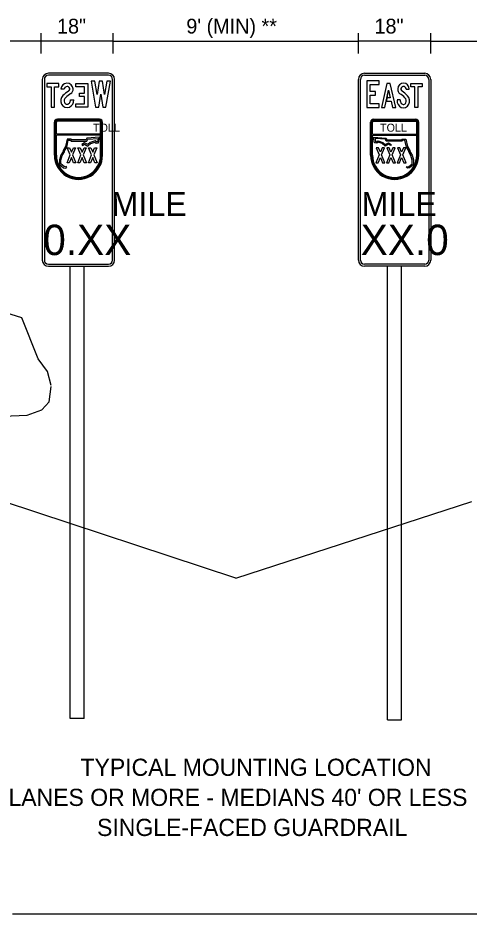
# Model space of a CAD drawing. Extents: x 57428 to 58066, y 11696 to 12105.
# Drawn here: x 57710.6 to 57796, y 11934.3 to 12103.9 of the extents above; entities that cross this region are included whole.
import ezdxf

# ---------------------------------------------------------------- set-up
doc = ezdxf.new("R2010")
doc.units = 0
for name, color, linetype in [('62', 7, 'Continuous'), ('DimLines_dp', 7, 'Continuous'), ('NonPlottingEle_dp', 7, 'Continuous'), ('SignPanel', 7, 'Continuous'), ('TextMisc', 7, 'Continuous'), ('TextTables', 7, 'Continuous'), ('XSGrdLine_ex', 7, 'Continuous')]:
    doc.layers.add(name, color=color, linetype=linetype)

msp = doc.modelspace()

# ---------------------------------------------------------------- linework, layer by layer
at = {"layer": '62'}
msp.add_lwpolyline([(57716.92, 12034.31), (57716.22, 12036.91), (57714.42, 12039.32), (57711.32, 12047.07), (57706.22, 12048.67), (57702.51, 12048.17), (57697.71, 12040.32), (57696.21, 12037.11), (57696.01, 12033.61), (57697.21, 12030.61), (57700.31, 12028.9), (57706.22, 12028.4), (57712.32, 12028.7), (57715.12, 12029.7), (57716.52, 12031.21), (57716.92, 12034.11)], dxfattribs=at)
at = {"layer": 'DimLines_dp'}
for p, q in [((57714.97, 12097.15), (57714.97, 12100.98)), ((57728.65, 12097.15), (57728.65, 12100.98)), ((57775.06, 12097.15), (57775.06, 12100.98)), ((57788.75, 12097.15), (57788.75, 12100.98)), ((57714.97, 12099.43), (57645.43, 12099.43)), ((57728.65, 12099.43), (57714.97, 12099.43)), ((57728.65, 12099.43), (57775.06, 12099.43)), ((57788.75, 12099.43), (57775.06, 12099.43)), ((57788.75, 12099.43), (57858.29, 12099.43))]:
    msp.add_line(p, q, dxfattribs=at)
at = {"layer": 'NonPlottingEle_dp'}
for p, q in [((57720.48, 12008.18), (57720.48, 12056.87)), ((57723.14, 12007.3), (57723.14, 12056.87)), ((57780.58, 12007.16), (57780.58, 12056.87)), ((57783.24, 12008.02), (57783.24, 12056.87)), ((57720.48, 11971.28), (57720.48, 12008.18)), ((57783.24, 11971.03), (57783.24, 12008.02)), ((57723.14, 11971.28), (57723.14, 12007.3)), ((57780.58, 11971.03), (57780.58, 12007.16)), ((57723.14, 11971.28), (57720.48, 11971.28)), ((57780.58, 11971.03), (57783.24, 11971.03))]:
    msp.add_line(p, q, dxfattribs=at)
at = {"layer": 'SignPanel'}
for p, q in [((57719.37, 12090.36), (57718.75, 12090.36)), ((57719.37, 12090.36), (57718.75, 12090.36)), ((57719.37, 12090.36), (57718.75, 12090.36)), ((57784.1, 12090.36), (57784.68, 12090.36)), ((57784.1, 12090.36), (57784.68, 12090.36)), ((57784.1, 12090.36), (57784.68, 12090.36)), ((57720.56, 12088.35), (57721.19, 12088.35)), ((57720.56, 12088.35), (57721.19, 12088.35)), ((57720.56, 12088.35), (57721.19, 12088.35)), ((57782.96, 12088.32), (57782.37, 12088.32)), ((57782.96, 12088.32), (57782.37, 12088.32)), ((57782.96, 12088.32), (57782.37, 12088.32)), ((57717.5, 12077.85), (57717.5, 12084.13)), ((57717.69, 12077.85), (57717.69, 12084.13)), ((57717.88, 12081.85), (57717.88, 12084.13)), ((57726.05, 12084.7), (57718.07, 12084.7)), ((57726.05, 12084.51), (57718.07, 12084.51)), ((57726.05, 12084.32), (57718.07, 12084.32)), ((57726.24, 12081.85), (57726.24, 12084.13)), ((57726.43, 12077.85), (57726.43, 12084.13)), ((57726.62, 12077.85), (57726.62, 12084.13)), ((57777.35, 12077.85), (57777.35, 12084.13)), ((57777.54, 12077.85), (57777.54, 12084.13)), ((57777.72, 12081.85), (57777.72, 12084.13)), ((57777.92, 12084.7), (57785.9, 12084.7)), ((57777.92, 12084.51), (57785.9, 12084.51)), ((57777.92, 12084.32), (57785.9, 12084.32)), ((57786.09, 12081.85), (57786.09, 12084.13)), ((57786.28, 12077.85), (57786.28, 12084.13)), ((57786.47, 12077.85), (57786.47, 12084.13)), ((57726.24, 12081.85), (57717.88, 12081.85)), ((57717.88, 12077.85), (57717.88, 12081.66)), ((57726.24, 12081.66), (57717.88, 12081.66)), ((57719.95, 12080.92), (57719.62, 12079.49)), ((57719.83, 12079.4), (57720.13, 12080.69)), ((57720.68, 12080.92), (57719.95, 12080.92)), ((57720.13, 12080.69), (57720.56, 12080.69)), ((57720.56, 12080.69), (57720.66, 12080.53)), ((57720.66, 12080.53), (57723.67, 12080.53)), ((57720.79, 12080.76), (57720.68, 12080.92)), ((57723.52, 12080.76), (57720.79, 12080.76)), ((57723.65, 12081.11), (57723.52, 12080.76)), ((57726.03, 12081.29), (57723.65, 12081.11)), ((57723.67, 12080.53), (57723.81, 12080.89)), ((57723.81, 12080.89), (57725.76, 12081.04)), ((57725.2, 12080.6), (57724.28, 12080.3)), ((57724.77, 12080.95), (57724.77, 12080.95)), ((57725.47, 12080.38), (57725.2, 12080.6)), ((57725.76, 12081.04), (57725.66, 12080.41)), ((57725.86, 12080.2), (57726.03, 12081.29)), ((57726.24, 12077.85), (57726.24, 12081.66)), ((57777.72, 12081.85), (57786.09, 12081.85)), ((57777.72, 12077.85), (57777.72, 12081.66)), ((57777.72, 12081.66), (57786.09, 12081.66)), ((57778.11, 12080.2), (57777.94, 12081.29)), ((57777.94, 12081.29), (57780.32, 12081.11)), ((57780.16, 12080.89), (57778.21, 12081.04)), ((57778.21, 12081.04), (57778.31, 12080.41)), ((57778.5, 12080.38), (57778.77, 12080.6)), ((57778.77, 12080.6), (57779.69, 12080.3)), ((57779.2, 12080.95), (57779.2, 12080.95)), ((57780.3, 12080.53), (57780.16, 12080.89)), ((57783.31, 12080.53), (57780.3, 12080.53)), ((57780.32, 12081.11), (57780.45, 12080.76)), ((57780.45, 12080.76), (57783.18, 12080.76)), ((57783.18, 12080.76), (57783.29, 12080.92)), ((57783.29, 12080.92), (57784.02, 12080.92)), ((57783.41, 12080.69), (57783.31, 12080.53)), ((57783.84, 12080.69), (57783.41, 12080.69)), ((57784.14, 12079.4), (57783.84, 12080.69)), ((57784.02, 12080.92), (57784.35, 12079.49)), ((57786.09, 12077.85), (57786.09, 12081.66)), ((57719.62, 12079.49), (57719.16, 12078.76)), ((57719.39, 12078.69), (57719.83, 12079.4)), ((57723.22, 12080.24), (57722.72, 12079.9)), ((57722.72, 12079.9), (57722.85, 12079.71)), ((57722.85, 12079.71), (57723.23, 12079.97)), ((57723.83, 12079.88), (57723.22, 12080.24)), ((57723.23, 12079.97), (57723.86, 12079.6)), ((57724.28, 12080.3), (57723.83, 12079.88)), ((57723.86, 12079.6), (57724.4, 12080.1)), ((57724.4, 12080.1), (57725.15, 12080.34)), ((57725.15, 12080.34), (57725.4, 12080.15)), ((57725.4, 12080.15), (57725.86, 12080.2)), ((57725.66, 12080.41), (57725.47, 12080.38)), ((57778.56, 12080.15), (57778.11, 12080.2)), ((57778.31, 12080.41), (57778.5, 12080.38)), ((57778.81, 12080.34), (57778.56, 12080.15)), ((57779.57, 12080.1), (57778.81, 12080.34)), ((57780.11, 12079.6), (57779.57, 12080.1)), ((57779.69, 12080.3), (57780.14, 12079.88)), ((57780.74, 12079.97), (57780.11, 12079.6)), ((57780.14, 12079.88), (57780.75, 12080.24)), ((57781.12, 12079.71), (57780.74, 12079.97)), ((57780.75, 12080.24), (57781.25, 12079.9)), ((57781.25, 12079.9), (57781.12, 12079.71)), ((57784.58, 12078.69), (57784.14, 12079.4)), ((57784.35, 12079.49), (57784.81, 12078.76)), ((57718.75, 12077.9), (57718.5, 12076.98)), ((57718.73, 12076.95), (57718.97, 12077.81)), ((57719.16, 12078.57), (57718.75, 12077.9)), ((57718.97, 12077.81), (57719.39, 12078.51)), ((57719.16, 12078.76), (57719.16, 12078.57)), ((57719.39, 12078.51), (57719.39, 12078.69)), ((57784.58, 12078.51), (57784.58, 12078.69)), ((57785, 12077.81), (57784.58, 12078.51)), ((57784.81, 12078.76), (57784.81, 12078.57)), ((57784.81, 12078.57), (57785.22, 12077.9)), ((57785.24, 12076.95), (57785, 12077.81)), ((57785.22, 12077.9), (57785.47, 12076.98)), ((57718.5, 12076.98), (57718.5, 12076.12)), ((57718.5, 12076.12), (57719.25, 12075.5)), ((57718.73, 12076.22), (57718.73, 12076.95)), ((57719.36, 12075.71), (57718.73, 12076.22)), ((57719.25, 12075.5), (57719.61, 12075.41)), ((57719.56, 12075.66), (57719.36, 12075.71)), ((57719.71, 12075.76), (57719.56, 12075.66)), ((57719.61, 12075.41), (57719.84, 12075.57)), ((57719.84, 12075.57), (57719.71, 12075.76)), ((57784.13, 12075.57), (57784.26, 12075.76)), ((57784.36, 12075.41), (57784.13, 12075.57)), ((57784.26, 12075.76), (57784.41, 12075.66)), ((57784.72, 12075.5), (57784.36, 12075.41)), ((57784.41, 12075.66), (57784.61, 12075.71)), ((57784.61, 12075.71), (57785.24, 12076.22)), ((57785.47, 12076.12), (57784.72, 12075.5)), ((57785.24, 12076.22), (57785.24, 12076.95)), ((57785.47, 12076.98), (57785.47, 12076.12))]:
    msp.add_line(p, q, dxfattribs=at)
for points in [[(57727.76, 12093.37), (57716.36, 12093.37)], [(57727.76, 12092.99), (57716.36, 12092.99)], [(57776.2, 12093.37), (57787.61, 12093.37)], [(57776.2, 12092.99), (57787.61, 12092.99)], [(57715.22, 12092.23), (57715.22, 12058.01)], [(57715.6, 12092.23), (57715.6, 12058.01)], [(57728.52, 12058.01), (57728.52, 12092.23)], [(57728.9, 12058.01), (57728.9, 12092.23)], [(57775.06, 12058.01), (57775.06, 12092.23)], [(57775.44, 12058.01), (57775.44, 12092.23)], [(57788.37, 12092.23), (57788.37, 12058.01)], [(57788.75, 12092.23), (57788.75, 12058.01)], [(57716.36, 12057.25), (57727.76, 12057.25)], [(57716.36, 12056.87), (57727.76, 12056.87)], [(57787.61, 12057.25), (57776.2, 12057.25)], [(57787.61, 12056.87), (57776.2, 12056.87)]]:
    msp.add_lwpolyline(points, dxfattribs=at)
for points in [[(57717.51, 12090.81), (57718.33, 12090.81), (57718.33, 12091.44), (57716.07, 12091.44), (57716.07, 12090.81), (57716.89, 12090.81), (57716.89, 12086.94), (57717.51, 12086.94)], [(57717.51, 12090.81), (57718.33, 12090.81), (57718.33, 12091.44), (57716.07, 12091.44), (57716.07, 12090.81), (57716.89, 12090.81), (57716.89, 12086.94), (57717.51, 12086.94)], [(57717.51, 12090.81), (57718.33, 12090.81), (57718.33, 12091.44), (57716.07, 12091.44), (57716.07, 12090.81), (57716.89, 12090.81), (57716.89, 12086.94), (57717.51, 12086.94)], [(57723.21, 12087.57), (57723.21, 12089.01), (57722.24, 12089.01), (57722.24, 12089.64), (57723.21, 12089.64), (57723.21, 12090.81), (57721.57, 12090.81), (57721.57, 12091.44), (57723.84, 12091.44), (57723.84, 12086.94), (57721.57, 12086.94), (57721.57, 12087.57)], [(57723.21, 12087.57), (57723.21, 12089.01), (57722.24, 12089.01), (57722.24, 12089.64), (57723.21, 12089.64), (57723.21, 12090.81), (57721.57, 12090.81), (57721.57, 12091.44), (57723.84, 12091.44), (57723.84, 12086.94), (57721.57, 12086.94), (57721.57, 12087.57)], [(57723.21, 12087.57), (57723.21, 12089.01), (57722.24, 12089.01), (57722.24, 12089.64), (57723.21, 12089.64), (57723.21, 12090.81), (57721.57, 12090.81), (57721.57, 12091.44), (57723.84, 12091.44), (57723.84, 12086.94), (57721.57, 12086.94), (57721.57, 12087.57)], [(57727, 12089.33), (57726.59, 12091.89), (57725.99, 12091.89), (57725.59, 12089.33), (57725.13, 12091.89), (57724.44, 12091.89), (57725.31, 12086.94), (57725.9, 12086.94), (57726.29, 12089.42), (57726.68, 12086.94), (57727.27, 12086.94), (57728.14, 12091.89), (57727.45, 12091.89)], [(57727, 12089.33), (57726.59, 12091.89), (57725.99, 12091.89), (57725.59, 12089.33), (57725.13, 12091.89), (57724.44, 12091.89), (57725.31, 12086.94), (57725.9, 12086.94), (57726.29, 12089.42), (57726.68, 12086.94), (57727.27, 12086.94), (57728.14, 12091.89), (57727.45, 12091.89)], [(57727, 12089.33), (57726.59, 12091.89), (57725.99, 12091.89), (57725.59, 12089.33), (57725.13, 12091.89), (57724.44, 12091.89), (57725.31, 12086.94), (57725.9, 12086.94), (57726.29, 12089.42), (57726.68, 12086.94), (57727.27, 12086.94), (57728.14, 12091.89), (57727.45, 12091.89)], [(57777.27, 12087.59), (57777.27, 12089.21), (57778.29, 12089.21), (57778.29, 12089.92), (57777.27, 12089.92), (57777.27, 12091.24), (57778.99, 12091.24), (57778.99, 12091.95), (57776.62, 12091.95), (57776.62, 12086.88), (57778.99, 12086.88), (57778.99, 12087.59)], [(57777.27, 12087.59), (57777.27, 12089.21), (57778.29, 12089.21), (57778.29, 12089.92), (57777.27, 12089.92), (57777.27, 12091.24), (57778.99, 12091.24), (57778.99, 12091.95), (57776.62, 12091.95), (57776.62, 12086.88), (57778.99, 12086.88), (57778.99, 12087.59)], [(57777.27, 12087.59), (57777.27, 12089.21), (57778.29, 12089.21), (57778.29, 12089.92), (57777.27, 12089.92), (57777.27, 12091.24), (57778.99, 12091.24), (57778.99, 12091.95), (57776.62, 12091.95), (57776.62, 12086.88), (57778.99, 12086.88), (57778.99, 12087.59)], [(57781.24, 12088.11), (57781.51, 12086.88), (57782.11, 12086.88), (57781.09, 12091.46), (57780.46, 12091.46), (57779.44, 12086.88), (57780.05, 12086.88), (57780.32, 12088.11)], [(57780.47, 12088.75), (57780.32, 12088.11), (57781.24, 12088.11), (57781.51, 12086.88), (57782.11, 12086.88), (57781.09, 12091.46), (57780.46, 12091.46), (57779.44, 12086.88), (57780.05, 12086.88), (57780.78, 12090.16), (57781.09, 12088.75)], [(57780.47, 12088.75), (57780.32, 12088.11), (57781.24, 12088.11), (57781.51, 12086.88), (57782.11, 12086.88), (57781.09, 12091.46), (57780.46, 12091.46), (57779.44, 12086.88), (57780.05, 12086.88), (57780.78, 12090.16), (57781.09, 12088.75)], [(57785.75, 12090.82), (57784.97, 12090.82), (57784.97, 12091.46), (57787.11, 12091.46), (57787.11, 12090.82), (57786.33, 12090.82), (57786.33, 12086.88), (57785.75, 12086.88)], [(57785.75, 12090.82), (57784.97, 12090.82), (57784.97, 12091.46), (57787.11, 12091.46), (57787.11, 12090.82), (57786.33, 12090.82), (57786.33, 12086.88), (57785.75, 12086.88)], [(57785.75, 12090.82), (57784.97, 12090.82), (57784.97, 12091.46), (57787.11, 12091.46), (57787.11, 12090.82), (57786.33, 12090.82), (57786.33, 12086.88), (57785.75, 12086.88)], [(57780.78, 12090.16), (57781.09, 12088.75), (57780.47, 12088.75)], [(57721.14, 12076.44), (57720.73, 12077.41), (57720.32, 12076.44), (57719.9, 12076.44), (57720.52, 12077.92), (57719.95, 12079.29), (57720.37, 12079.29), (57720.73, 12078.43), (57721.09, 12079.29), (57721.52, 12079.29), (57720.95, 12077.92), (57721.57, 12076.44)], [(57723.16, 12076.44), (57722.75, 12077.41), (57722.34, 12076.44), (57721.91, 12076.44), (57722.53, 12077.92), (57721.96, 12079.29), (57722.39, 12079.29), (57722.75, 12078.43), (57723.11, 12079.29), (57723.53, 12079.29), (57722.96, 12077.92), (57723.58, 12076.44)], [(57725.17, 12076.44), (57724.76, 12077.41), (57724.36, 12076.44), (57723.93, 12076.44), (57724.55, 12077.92), (57723.98, 12079.29), (57724.41, 12079.29), (57724.76, 12078.43), (57725.12, 12079.29), (57725.55, 12079.29), (57724.98, 12077.92), (57725.6, 12076.44)], [(57778.8, 12076.44), (57779.21, 12077.41), (57779.61, 12076.44), (57780.04, 12076.44), (57779.42, 12077.92), (57779.99, 12079.29), (57779.56, 12079.29), (57779.21, 12078.43), (57778.85, 12079.29), (57778.42, 12079.29), (57778.99, 12077.92), (57778.37, 12076.44)], [(57780.81, 12076.44), (57781.22, 12077.41), (57781.63, 12076.44), (57782.06, 12076.44), (57781.43, 12077.92), (57782.01, 12079.29), (57781.58, 12079.29), (57781.22, 12078.43), (57780.86, 12079.29), (57780.44, 12079.29), (57781.01, 12077.92), (57780.39, 12076.44)], [(57782.83, 12076.44), (57783.24, 12077.41), (57783.65, 12076.44), (57784.07, 12076.44), (57783.45, 12077.92), (57784.02, 12079.29), (57783.6, 12079.29), (57783.24, 12078.43), (57782.88, 12079.29), (57782.45, 12079.29), (57783.02, 12077.92), (57782.4, 12076.44)]]:
    msp.add_lwpolyline(points, close=True, dxfattribs=at)
for centre, radius, start, end in [((57716.36, 12092.23), 1.14, 90, 180), ((57716.36, 12092.23), 0.76, 90, 180), ((57727.76, 12092.23), 1.14, 0, 90), ((57727.76, 12092.23), 0.76, 0, 90), ((57776.2, 12092.23), 1.14, 90, 180), ((57776.2, 12092.23), 0.76, 90, 180), ((57787.61, 12092.23), 1.14, 0, 90), ((57787.61, 12092.23), 0.76, 0, 90), ((57716.36, 12058.01), 1.14, 180, 270), ((57716.36, 12058.01), 0.76, 180, 270), ((57727.76, 12058.01), 1.14, 270, 0), ((57727.76, 12058.01), 0.76, 270, 0), ((57776.2, 12058.01), 1.14, 180, 270), ((57776.2, 12058.01), 0.76, 180, 270), ((57787.61, 12058.01), 1.14, 270, 360), ((57787.61, 12058.01), 0.76, 270, 360)]:
    msp.add_arc(centre, radius, start, end, dxfattribs=at)
for centre, major_axis, ratio, start_param, end_param in [((57719.9, 12090.33), (0, -1.17), 0.981197, 1.634182, 4.688511), ((57719.9, 12090.33), (0, -1.17), 0.981197, 1.634182, 4.688511), ((57719.9, 12090.33), (0, -1.17), 0.981197, 1.634182, 4.688511), ((57719.91, 12090.32), (0, -0.55), 0.981197, 2.28404, 4.637874), ((57719.91, 12090.32), (0, -0.55), 0.981197, 2.28404, 4.637874), ((57719.91, 12090.32), (0, -0.55), 0.981197, 2.28404, 4.637874), ((57783.59, 12090.33), (0, 1.19), 0.91923, 4.736267, 7.790596), ((57783.59, 12090.33), (0, 1.19), 0.91923, 4.736267, 7.790596), ((57783.59, 12090.33), (0, 1.19), 0.91923, 4.736267, 7.790596), ((57783.59, 12090.32), (0, 0.558), 0.91923, 4.786904, 7.140738), ((57783.59, 12090.32), (0, 0.558), 0.91923, 4.786904, 7.140738), ((57783.59, 12090.32), (0, 0.558), 0.91923, 4.786904, 7.140738), ((57720.1, 12088.17), (0, -1.4), 0.981197, 3.939023, 5.163791), ((57720.1, 12088.17), (0, -1.4), 0.981197, 3.939023, 5.163791), ((57720.1, 12088.17), (0, -1.4), 0.981197, 3.939023, 5.163791), ((57722.22, 12086.2), (0, -4.32), 0.981197, 3.642536, 3.961892), ((57722.22, 12086.2), (0, -4.32), 0.981197, 3.642536, 3.961892), ((57722.22, 12086.2), (0, -4.32), 0.981197, 3.642536, 3.961892), ((57722.75, 12085.51), (0, -4.56), 0.981197, 3.63779, 3.909641), ((57722.75, 12085.51), (0, -4.56), 0.981197, 3.63779, 3.909641), ((57722.75, 12085.51), (0, -4.56), 0.981197, 3.63779, 3.909641), ((57719.97, 12090.39), (0, -0.453), 0.981197, 0.484634, 2.267813), ((57719.97, 12090.39), (0, -0.453), 0.981197, 0.484634, 2.267813), ((57719.97, 12090.39), (0, -0.453), 0.981197, 0.484634, 2.267813), ((57720.02, 12090.37), (0, -1.05), 0.981197, 0.629826, 1.606762), ((57720.02, 12090.37), (0, -1.05), 0.981197, 0.629826, 1.606762), ((57720.02, 12090.37), (0, -1.05), 0.981197, 0.629826, 1.606762), ((57783.48, 12090.37), (0, 1.07), 0.91923, 1.534831, 2.511766), ((57783.48, 12090.37), (0, 1.07), 0.91923, 1.534831, 2.511766), ((57783.48, 12090.37), (0, 1.07), 0.91923, 1.534831, 2.511766), ((57780.88, 12085.43), (0, 4.63), 0.91923, 5.515137, 5.786988), ((57780.88, 12085.43), (0, 4.63), 0.91923, 5.515137, 5.786988), ((57780.88, 12085.43), (0, 4.63), 0.91923, 5.515137, 5.786988), ((57783.52, 12090.39), (0, 0.46), 0.91923, 0.87378, 2.656959), ((57783.52, 12090.39), (0, 0.46), 0.91923, 0.87378, 2.656959), ((57783.52, 12090.39), (0, 0.46), 0.91923, 0.87378, 2.656959), ((57781.39, 12086.13), (0, 4.39), 0.91923, 5.462886, 5.782242), ((57781.39, 12086.13), (0, 4.39), 0.91923, 5.462886, 5.782242), ((57781.39, 12086.13), (0, 4.39), 0.91923, 5.462886, 5.782242), ((57783.41, 12088.13), (0, 1.42), 0.91923, 4.260987, 5.485755), ((57783.41, 12088.13), (0, 1.42), 0.91923, 4.260987, 5.485755), ((57783.41, 12088.13), (0, 1.42), 0.91923, 4.260987, 5.485755), ((57719.94, 12088.1), (0, -1.23), 0.981197, 5.173086, 6.638731), ((57719.94, 12088.1), (0, -1.23), 0.981197, 5.173086, 6.638731), ((57719.94, 12088.1), (0, -1.23), 0.981197, 5.173086, 6.638731), ((57720.11, 12088.17), (0, -0.78), 0.981197, 3.79238, 5.170369), ((57720.11, 12088.17), (0, -0.78), 0.981197, 3.79238, 5.170369), ((57720.11, 12088.17), (0, -0.78), 0.981197, 3.79238, 5.170369), ((57719.92, 12088.09), (0, -0.572), 0.981197, 5.194718, 7.162991), ((57719.92, 12088.09), (0, -0.572), 0.981197, 5.194718, 7.162991), ((57719.92, 12088.09), (0, -0.572), 0.981197, 5.194718, 7.162991), ((57719.68, 12088.31), (0, -0.897), 0.981197, 0.859453, 1.616836), ((57719.68, 12088.31), (0, -0.897), 0.981197, 0.859453, 1.616836), ((57719.68, 12088.31), (0, -0.897), 0.981197, 0.859453, 1.616836), ((57719.74, 12088.29), (0, -1.47), 0.981197, 0.439911, 1.615229), ((57719.74, 12088.29), (0, -1.47), 0.981197, 0.439911, 1.615229), ((57719.74, 12088.29), (0, -1.47), 0.981197, 0.439911, 1.615229), ((57783.74, 12088.25), (0, 1.5), 0.91923, 1.526364, 2.701682), ((57783.74, 12088.25), (0, 1.5), 0.91923, 1.526364, 2.701682), ((57783.74, 12088.25), (0, 1.5), 0.91923, 1.526364, 2.701682), ((57783.8, 12088.28), (0, 0.911), 0.91923, 1.524757, 2.28214), ((57783.8, 12088.28), (0, 0.911), 0.91923, 1.524757, 2.28214), ((57783.8, 12088.28), (0, 0.911), 0.91923, 1.524757, 2.28214), ((57783.56, 12088.07), (0, 1.24), 0.91923, 2.786047, 4.251692), ((57783.56, 12088.07), (0, 1.24), 0.91923, 2.786047, 4.251692), ((57783.56, 12088.07), (0, 1.24), 0.91923, 2.786047, 4.251692), ((57783.58, 12088.05), (0, 0.581), 0.91923, 2.261787, 4.23006), ((57783.58, 12088.05), (0, 0.581), 0.91923, 2.261787, 4.23006), ((57783.58, 12088.05), (0, 0.581), 0.91923, 2.261787, 4.23006), ((57783.4, 12088.13), (0, 0.792), 0.91923, 4.254409, 5.632398), ((57783.4, 12088.13), (0, 0.792), 0.91923, 4.254409, 5.632398), ((57783.4, 12088.13), (0, 0.792), 0.91923, 4.254409, 5.632398), ((57718.07, 12084.13), (0, 0.57), 0.9997, 0, 1.570796), ((57718.07, 12084.13), (0, 0.38), 0.9997, 0, 1.570796), ((57718.07, 12084.13), (0, 0.19), 0.9997, 0, 1.570796), ((57726.05, 12084.13), (0, 0.57), 0.9997, 4.712389, 6.283185), ((57726.05, 12084.13), (0, 0.38), 0.9997, 4.712389, 6.283185), ((57726.05, 12084.13), (0, 0.19), 0.9997, 4.712389, 6.283185), ((57777.92, 12084.13), (0, 0.57), 0.9997, 0, 1.570796), ((57777.92, 12084.13), (0, 0.38), 0.9997, 0, 1.570796), ((57777.92, 12084.13), (0, 0.19), 0.9997, 0, 1.570796), ((57785.9, 12084.13), (0, 0.57), 0.9997, 4.712389, 6.283185), ((57785.9, 12084.13), (0, 0.38), 0.9997, 4.712389, 6.283185), ((57785.9, 12084.13), (0, 0.19), 0.9997, 4.712389, 6.283185), ((57722.06, 12077.86), (0, 4.56), 0.9997, 1.570796, 4.712389), ((57722.06, 12077.86), (0, 4.37), 0.9997, 1.570796, 4.712389), ((57722.06, 12077.86), (0, 4.18), 0.9997, 1.570796, 4.712389), ((57781.91, 12077.86), (0, -4.56), 0.9997, 4.712389, 7.853982), ((57781.91, 12077.86), (0, -4.37), 0.9997, 4.712389, 7.853982), ((57781.91, 12077.86), (0, -4.18), 0.9997, 4.712389, 7.853982)]:
    msp.add_ellipse(centre, major_axis=major_axis, ratio=ratio, start_param=start_param, end_param=end_param, dxfattribs=at)
at = {"layer": 'TextMisc'}
msp.add_line((58065.89, 11934.25), (57709.55, 11934.25), dxfattribs=at)
at = {"layer": 'XSGrdLine_ex'}
for q in [(57707.87, 12012.33), (57796.52, 12012.33)]:
    msp.add_line((57751.86, 11997.83), q, dxfattribs=at)

# ---------------------------------------------------------------- texts
at = {"layer": 'DimLines_dp'}
for s, p in [('18"', (57718, 12100.9)), ("9' (MIN) **", (57742.48, 12100.9)), ('18"', (57778.1, 12100.9))]:
    msp.add_text(s, height=2.8, dxfattribs=at).set_placement(p)
at = {"layer": 'SignPanel'}
for s, height, p in [('TOLL', 1.519, (57724.82, 12082.32)), ('TOLL', 1.519, (57779.15, 12082.32)), ('MILE', 4.562, (57728.32, 12066.37)), ('MILE', 4.562, (57775.65, 12066.37)), ('0.XX', 5.75, (57715.39, 12058.97)), ('XX.0', 5.75, (57775.49, 12058.97))]:
    msp.add_text(s, height=height, rotation=360, dxfattribs=at).set_placement(p)
at = {"layer": 'TextTables'}
for s, p in [('TYPICAL MOUNTING LOCATION', (57722.45, 11960.41)), ("6 LANES OR MORE - MEDIANS 40' OR LESS", (57705.19, 11954.72)), ('SINGLE-FACED GUARDRAIL', (57725.58, 11949.03))]:
    msp.add_text(s, height=3.2524, dxfattribs=at).set_placement(p)

doc.saveas('drawing.dxf')
